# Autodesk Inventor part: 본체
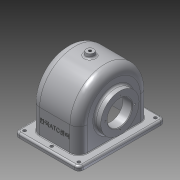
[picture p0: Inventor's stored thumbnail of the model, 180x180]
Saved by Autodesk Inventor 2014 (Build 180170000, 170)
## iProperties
Created: 2015-09
Part Number: 본체
Material: 알루미늄 6061
Document SubType Name: Modeling
Designer: USER
Density: 2.71 g/cm^3
Appearance: 알루미늄 - 평지
Mass: 723.544 g
Surface Area: 889.793 cm^2
Volume: 266.991 cm^3
Author: USER
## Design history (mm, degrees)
sketch "스케치2"
  geometry: L1 (-57, 0)-(-57, -40); L2 (57, 0)-(57, -40); L3 (57, -40)-(-57, -40); A1 r 57 centre (0, 0) between (57, 0) and (-57, 0); 1 further point
  constraints: 6 end point, 2 point on circle, 2 tangent, 1 centre point, 1 coincident, 1 parallel, 1 vertical
  dimensions: "d3" = 114 diameter of A1; "d4" = 40 distance of L1.start L1.end; "d5" = 40 distance of L2.start L2.end
extrude "돌출1" new body sketch "스케치2" distance "d6" = 77; taper "d7" = 0 deg
node "작업 평면1"
sketch "스케치3"
  geometry: L1 (0, 57)-(77, 57) reference; L2 (0, -57)-(77, -57) reference; L3 (14, 0)-(63, 0); L4 (38.5, 57)-(38.5, -57); L5 (-13.5, 0)-(90.5, 0); L6 (-13.5, 70)-(-13.5, -70); L7 (-13.5, 70)-(90.5, 70); L8 (90.5, 70)-(90.5, -70); L9 (90.5, -70)-(-13.5, -70); L10 (0, -57)-(0, 57) reference; L11 (77, 57)-(77, -57) reference; 2 further points
  constraints: 14 end point, 5 midpoint, 4 perpendicular
  dimensions: "d11" = 104 distance of L5.start L5.end; "d12" = 140 distance of L6.start L6.end; "d13" = 104 distance of L6.start L7.end; "d14" = 140 distance of L7.end L8.end
extrude "돌출2" join sketch "스케치3" distance "d15" = 7; taper "d16" = 0 deg
fillet "모깎기2" dims "d17" = 7
fillet "모깎기3" dims "d18" = 3
sketch "스케치4"
  geometry: L1 (-13.5, 63)-(-13.5, -63) reference; L2 (83.5, 70)-(-6.5, 70) reference; L3 (90.5, -63)-(90.5, 63) reference; L4 (-6.5, -70)-(83.5, -70) reference; C1 r 2.5 at (38.5, 62); C2 r 2.5 at (-5.5, 62); C3 r 2.5 at (82.5, 62); C4 r 2.5 at (-5.5, -62); C5 r 2.5 at (38.5, -62); C6 r 2.5 at (82.5, -62); 1 further point
  constraints: 6 centre point, 2 horizontal alignment
  dimensions: "d24" = 5 diameter of C1; "d27" = 5 diameter of C2; "d28" = 5 diameter of C3; "d29" = 5 diameter of C4; "d30" = 5 diameter of C5; "d31" = 5 diameter of C6; "d32" = 8 distance from line of C2.centre L1; "d33" = 8 distance from line of L2 C2.centre; "d34" = 8 distance from line of L2 C3.centre; "d35" = 8 distance from line of C3.centre L3; "d36" = 44 distance of C1.centre C2.centre; "d37" = 44 distance of C3.centre C1.centre (derived); "d38" = 8 distance from line of C4.centre L1; "d39" = 8 distance from line of L4 C4.centre; "d40" = 44 distance of C5.centre C4.centre; "d41" = 8 distance from line of L4 C6.centre; "d42" = 8 distance from line of L3 C6.centre
extrude "돌출3" cut sketch "스케치4" distance "d43" = 7; taper "d44" = 0 deg
node "작업 평면3"
sketch "스케치12"
  geometry: C1 r 31 at (0, 0); A1 r 57 centre (0, 0) between (0, 57) and (0, -57) reference
  constraints: 1 centre point, 1 coincident
  dimensions: "d73" = 62 diameter of C1
extrude "돌출8" join sketch "스케치12" distance "d74" = 10; taper "d75" = 0 deg
node "작업 평면5"
sketch "스케치13"
  geometry: L1 (-57, -40)-(-57, 0) reference; L2 (-63, -47)-(63, -47) reference; L3 (57, 0)-(57, -40) reference; L4 (-51, -47)-(51, -47); L5 (-51, 0)-(-51, -47); L6 (51, 0)-(51, -47); A1 r 57 centre (0, 0) between (57, 0) and (-57, 0) reference; A2 r 51 centre (0, 0) between (51, 0) and (-51, 0); 1 further point
  constraints: 6 end point, 2 perpendicular, 2 point on circle, 2 point on line, 2 tangent, 1 centre point, 1 collinear
  dimensions: "d129" = 6 radial gap between concentric circles of A2 A1; "d130" = 102 distance between parallel lines of L6 L5 (derived)
extrude "돌출9" cut sketch "스케치13" stored distance "d80" = 67; taper "d81" = 0 deg
sketch "스케치14"
  geometry: L1 (0, 0)-(0, 57) reference; L2 (0, 0)-(0, -40) reference; L3 (-87, 31)-(-87, -31) reference; L4 (0, 0)-(-87, 0); L5 (-19, 0)-(-19, 28); L6 (-19, 28)-(0, 43.943); L7 (0, 0)-(0, 43.943); 1 further point
  constraints: 8 end point, 2 point on line, 1 collinear, 1 midpoint, 1 perpendicular
  dimensions: "d82" = 56 diameter of L5.end L4; "d83" = 50 deg angle of L5 L6; "d84" = 19 distance between parallel lines of L5 L1
revolve "회전2" sketch "스케치14" stored, may be unused: angle "d85" = 90 deg
sketch "스케치16"
  geometry: C1 r 33 at (0, 0); A1 r 57 centre (0, 0) between (0, -57) and (0, 57) reference
  constraints: 1 centre point, 1 coincident
  dimensions: "d95" = 66 diameter of C1
extrude "돌출10" cut sketch "스케치16" distance "d96" = 3; taper "d97" = 0 deg
sketch "스케치17"
  geometry: C1 r 31 at (0, 0) reference; C2 r 20 at (0, 0)
  constraints: 1 centre point, 1 coincident
  dimensions: "d98" = 40 diameter of C2
extrude "돌출11" cut sketch "스케치17" stored distance "d99" = 3; taper "d100" = 0 deg
sketch "스케치18"
  geometry: L1 (0, 33)-(0, -33) reference; L2 (-87, -20)-(-87, 20) reference; L3 (0, 0)-(0, 57) reference; L4 (-19, 28)-(-5, 39.747) reference; L5 (-5.263, 33)-(0, 37.416); L6 (0, 0)-(-87, 0); L7 (0, 33)-(-3, 33) reference; L8 (-3, 33)-(-3, -33) reference; L9 (-5.263, 33)-(-3, 33); L10 (-3, 33)-(-3, 0); L11 (0, 37.416)-(0, 0)
  constraints: 10 end point, 2 midpoint, 1 collinear, 1 parallel, 1 perpendicular, 1 point on line
  dimensions: "d101" = 5 distance between parallel lines of L4 L5
revolve "회전3" sketch "스케치18" stored, may be unused: angle "d102" = 90 deg
sketch "스케치19" dims "d103" = 48
  geometry: C1 r 20 at (0, 0) reference; C2 r 31 at (0, 0) reference; 2 further points
  constraints: 2 horizontal alignment, 1 coincident, 2 other
hole "구멍1" sketch "스케치19" at (-24, 0) diameter "d104" = 2.459; stored, may be unused: countersink angle "d108" = 90 deg, drill point angle "d110" = 118 deg; dims "d105" = 6, "d106" = 4, "d107" = 2, "d109" = 8
sketch "스케치20" dims "d114" = 56
  geometry: C1 r 20 at (0, 0) reference; C2 r 33 at (0, 0) reference; 2 further points
  constraints: 2 horizontal alignment, 1 coincident, 2 other
hole "구멍2" sketch "스케치20" at (28, 0) diameter "d115" = 2.459; stored, may be unused: countersink angle "d119" = 90 deg, drill point angle "d121" = 118 deg; dims "d116" = 7, "d117" = 4, "d118" = 2, "d120" = 9
sketch "스케치21"
  geometry: L1 (0, -40)-(0, 0) reference; L2 (0, -37.416)-(0, 37.416) reference; L3 (-6.5, -47)-(-13.5, -47) reference; 2 further points
  constraints: 1 other
  dimensions: "d125" = 30 vertical distance of point (38.5, -17) L3.end; "d126" = 38.5 distance from line of L1 point (38.5, -17)
feature "엠보싱1" sketch "스케치21" dims "d3" = 114, "d4" = 40, "d5" = 40, "d127" = 0.5, "d128" = 0
fillet "모깎기6" dims "d131" = 14
fillet "모깎기7" dims "d132" = 9
fillet "모깎기8" dims "d133" = 0.5
node "작업 평면6"
sketch "스케치22"
  geometry: L1 (83.5, 70)-(-6.5, 70) reference; L2 (-13.5, 63)-(-13.5, -63) reference; C1 r 6 at (38.5, 0); 3 further points
  constraints: 2 midpoint, 1 centre point, 1 horizontal alignment, 1 vertical alignment
  dimensions: "d135" = 12 diameter of C1
extrude "돌출12" join sketch "스케치22" stored distance "d136" = 3; taper "d137" = 10 deg
sketch "스케치23"
  geometry: C1 r 6 at (0, 0) reference; 2 further points
  constraints: 1 coincident
hole "구멍3" sketch "스케치23" at (0, 0) diameter "d138" = 4.459; stored, may be unused: countersink angle "d142" = 90 deg, drill point angle "d144" = 118 deg; dims "d139" = 40, "d140" = 4, "d141" = 2, "d143" = 9
fillet "모깎기9" dims "d145" = 3
fillet "모깎기10" dims "d146" = 1
fillet "모깎기11" dims "d147" = 3
chamfer "모따기1" distance "d148" = 1; stored, may be unused: second distance "d149" = 2, angle "d150" = 45 deg
node "솔리드1"
pattern_circular "원형 패턴1" dims angle "d112" = 360 deg
pattern_circular "원형 패턴2" dims angle "d123" = 360 deg
node "투영된 루프1"
other parameters: "d134" = 63
